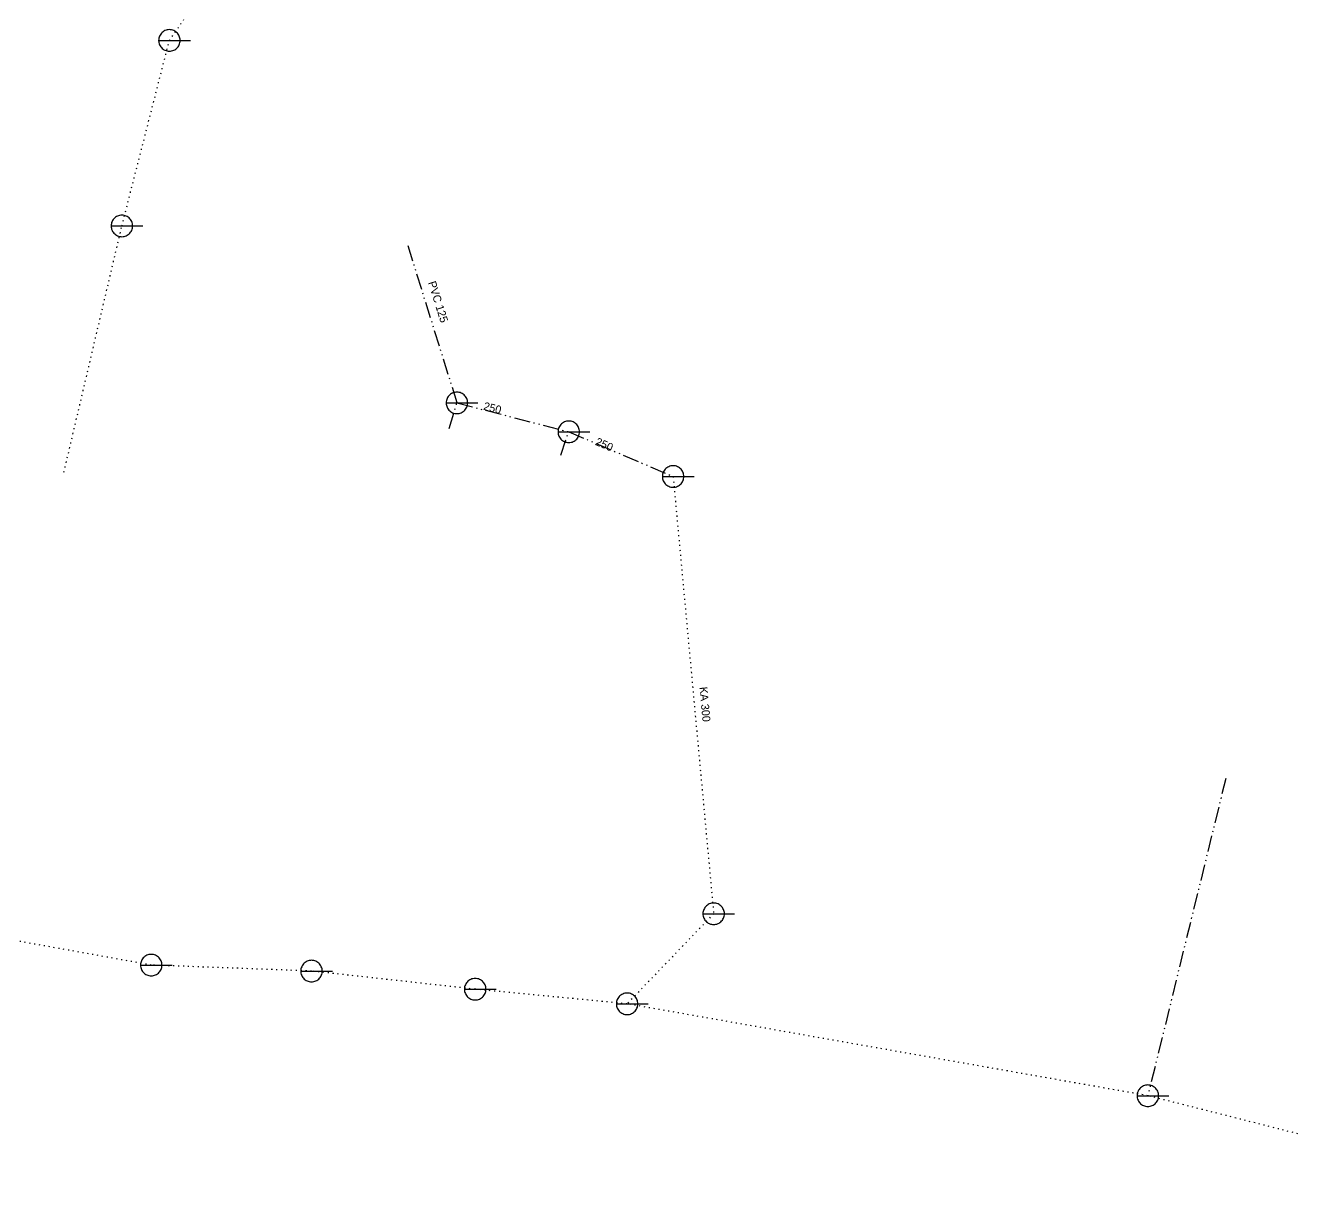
# Model space of a CAD drawing. Extents: x -688177 to -687620, y -1056713 to -1056287.
# Drawn here: x -688067.1 to -687948.5, y -1056712.1 to -1056603.9 of the extents above; entities that cross this region are included whole.
import ezdxf

# ---------------------------------------------------------------- set-up
doc = ezdxf.new("R2010")
doc.units = 0
doc.header["$LTSCALE"] = 0.3
doc.linetypes.add('DASH_DOUBLE_DOT', pattern=[9.2, 5, -1.2, 0.3, -1.2, 0.3, -1.2])
doc.linetypes.add('DOTTED', pattern=[1.5, 0.3, -1.2])
for name, color, linetype, lineweight in [('12', 7, 'Continuous', 13), ('31', 7, 'DOTTED', 13), ('41', 7, 'DOTTED', 13), ('45', 7, 'DASH_DOUBLE_DOT', 13), ('46', 7, 'DOTTED', 13), ('51', 7, 'DASH_DOUBLE_DOT', 13)]:
    doc.layers.add(name, color=color, linetype=linetype, lineweight=lineweight)
doc.layers.add('18', color=7, linetype='Continuous')
doc.layers.add('19', color=7, linetype='Continuous')

msp = doc.modelspace()

# ---------------------------------------------------------------- linework, layer by layer
at = {"layer": '12'}
for p, q in [((-688054.638, -1056605.28), (-688051.662, -1056605.28)), ((-688059.088, -1056622.67), (-688056.112, -1056622.67)), ((-688027.688, -1056639.25), (-688024.712, -1056639.25)), ((-688017.208, -1056641.96), (-688014.232, -1056641.96)), ((-688007.428, -1056646.15), (-688004.452, -1056646.15)), ((-688003.628, -1056687.13), (-688000.652, -1056687.13)), ((-688056.338, -1056691.94), (-688053.362, -1056691.94)), ((-688041.318, -1056692.5), (-688038.342, -1056692.5)), ((-688025.978, -1056694.2), (-688023.002, -1056694.2)), ((-688011.738, -1056695.57), (-688008.762, -1056695.57)), ((-687962.938, -1056704.18), (-687959.962, -1056704.18))]:
    msp.add_line(p, q, dxfattribs=at)
for points in [[(-688053.63, -1056604.272), (-688053.735, -1056604.278), (-688053.839, -1056604.294), (-688053.941, -1056604.322), (-688054.04, -1056604.36), (-688054.134, -1056604.407), (-688054.222, -1056604.465), (-688054.304, -1056604.531), (-688054.379, -1056604.606), (-688054.445, -1056604.688), (-688054.503, -1056604.776), (-688054.55, -1056604.87), (-688054.588, -1056604.969), (-688054.616, -1056605.071), (-688054.632, -1056605.175), (-688054.638, -1056605.28), (-688054.632, -1056605.385), (-688054.616, -1056605.49), (-688054.588, -1056605.592), (-688054.55, -1056605.69), (-688054.503, -1056605.784), (-688054.445, -1056605.873), (-688054.379, -1056605.955), (-688054.304, -1056606.029), (-688054.222, -1056606.095), (-688054.134, -1056606.153), (-688054.04, -1056606.201), (-688053.941, -1056606.239), (-688053.839, -1056606.266), (-688053.735, -1056606.282), (-688053.63, -1056606.288), (-688053.525, -1056606.282), (-688053.42, -1056606.266), (-688053.318, -1056606.239), (-688053.22, -1056606.201), (-688053.126, -1056606.153), (-688053.037, -1056606.095), (-688052.955, -1056606.029), (-688052.881, -1056605.955), (-688052.815, -1056605.873), (-688052.757, -1056605.784), (-688052.709, -1056605.69), (-688052.671, -1056605.592), (-688052.644, -1056605.49), (-688052.628, -1056605.385), (-688052.622, -1056605.28), (-688052.628, -1056605.175), (-688052.644, -1056605.071), (-688052.671, -1056604.969), (-688052.709, -1056604.87), (-688052.757, -1056604.776), (-688052.815, -1056604.688), (-688052.881, -1056604.606), (-688052.955, -1056604.531), (-688053.037, -1056604.465), (-688053.126, -1056604.407), (-688053.22, -1056604.36), (-688053.318, -1056604.322), (-688053.42, -1056604.294), (-688053.525, -1056604.278)], [(-688058.08, -1056621.662), (-688058.185, -1056621.668), (-688058.289, -1056621.684), (-688058.391, -1056621.712), (-688058.49, -1056621.75), (-688058.584, -1056621.797), (-688058.672, -1056621.855), (-688058.754, -1056621.921), (-688058.829, -1056621.996), (-688058.895, -1056622.078), (-688058.953, -1056622.166), (-688059, -1056622.26), (-688059.038, -1056622.359), (-688059.066, -1056622.461), (-688059.082, -1056622.565), (-688059.088, -1056622.67), (-688059.082, -1056622.775), (-688059.066, -1056622.88), (-688059.038, -1056622.982), (-688059, -1056623.08), (-688058.953, -1056623.174), (-688058.895, -1056623.263), (-688058.829, -1056623.345), (-688058.754, -1056623.419), (-688058.672, -1056623.485), (-688058.584, -1056623.543), (-688058.49, -1056623.591), (-688058.391, -1056623.629), (-688058.289, -1056623.656), (-688058.185, -1056623.672), (-688058.08, -1056623.678), (-688057.975, -1056623.672), (-688057.87, -1056623.656), (-688057.768, -1056623.629), (-688057.67, -1056623.591), (-688057.576, -1056623.543), (-688057.487, -1056623.485), (-688057.405, -1056623.419), (-688057.331, -1056623.345), (-688057.265, -1056623.263), (-688057.207, -1056623.174), (-688057.159, -1056623.08), (-688057.121, -1056622.982), (-688057.094, -1056622.88), (-688057.078, -1056622.775), (-688057.072, -1056622.67), (-688057.078, -1056622.565), (-688057.094, -1056622.461), (-688057.121, -1056622.359), (-688057.159, -1056622.26), (-688057.207, -1056622.166), (-688057.265, -1056622.078), (-688057.331, -1056621.996), (-688057.405, -1056621.921), (-688057.487, -1056621.855), (-688057.576, -1056621.797), (-688057.67, -1056621.75), (-688057.768, -1056621.712), (-688057.87, -1056621.684), (-688057.975, -1056621.668)], [(-688026.68, -1056638.242), (-688026.785, -1056638.248), (-688026.889, -1056638.264), (-688026.991, -1056638.292), (-688027.09, -1056638.33), (-688027.184, -1056638.377), (-688027.272, -1056638.435), (-688027.354, -1056638.501), (-688027.429, -1056638.576), (-688027.495, -1056638.658), (-688027.553, -1056638.746), (-688027.6, -1056638.84), (-688027.638, -1056638.939), (-688027.666, -1056639.041), (-688027.682, -1056639.145), (-688027.688, -1056639.25), (-688027.682, -1056639.355), (-688027.666, -1056639.46), (-688027.638, -1056639.562), (-688027.6, -1056639.66), (-688027.553, -1056639.754), (-688027.495, -1056639.843), (-688027.429, -1056639.925), (-688027.354, -1056639.999), (-688027.272, -1056640.065), (-688027.184, -1056640.123), (-688027.09, -1056640.171), (-688026.991, -1056640.209), (-688026.889, -1056640.236), (-688026.785, -1056640.252), (-688026.68, -1056640.258), (-688026.575, -1056640.252), (-688026.47, -1056640.236), (-688026.368, -1056640.209), (-688026.27, -1056640.171), (-688026.176, -1056640.123), (-688026.087, -1056640.065), (-688026.005, -1056639.999), (-688025.931, -1056639.925), (-688025.865, -1056639.843), (-688025.807, -1056639.754), (-688025.759, -1056639.66), (-688025.721, -1056639.562), (-688025.694, -1056639.46), (-688025.678, -1056639.355), (-688025.672, -1056639.25), (-688025.678, -1056639.145), (-688025.694, -1056639.041), (-688025.721, -1056638.939), (-688025.759, -1056638.84), (-688025.807, -1056638.746), (-688025.865, -1056638.658), (-688025.931, -1056638.576), (-688026.005, -1056638.501), (-688026.087, -1056638.435), (-688026.176, -1056638.377), (-688026.27, -1056638.33), (-688026.368, -1056638.292), (-688026.47, -1056638.264), (-688026.575, -1056638.248)], [(-688016.2, -1056640.952), (-688016.305, -1056640.958), (-688016.409, -1056640.974), (-688016.511, -1056641.002), (-688016.61, -1056641.04), (-688016.704, -1056641.087), (-688016.792, -1056641.145), (-688016.874, -1056641.211), (-688016.949, -1056641.286), (-688017.015, -1056641.368), (-688017.073, -1056641.456), (-688017.12, -1056641.55), (-688017.158, -1056641.649), (-688017.186, -1056641.751), (-688017.202, -1056641.855), (-688017.208, -1056641.96), (-688017.202, -1056642.065), (-688017.186, -1056642.17), (-688017.158, -1056642.272), (-688017.12, -1056642.37), (-688017.073, -1056642.464), (-688017.015, -1056642.553), (-688016.949, -1056642.635), (-688016.874, -1056642.709), (-688016.792, -1056642.775), (-688016.704, -1056642.833), (-688016.61, -1056642.881), (-688016.511, -1056642.919), (-688016.409, -1056642.946), (-688016.305, -1056642.962), (-688016.2, -1056642.968), (-688016.095, -1056642.962), (-688015.99, -1056642.946), (-688015.888, -1056642.919), (-688015.79, -1056642.881), (-688015.696, -1056642.833), (-688015.607, -1056642.775), (-688015.525, -1056642.709), (-688015.451, -1056642.635), (-688015.385, -1056642.553), (-688015.327, -1056642.464), (-688015.279, -1056642.37), (-688015.241, -1056642.272), (-688015.214, -1056642.17), (-688015.198, -1056642.065), (-688015.192, -1056641.96), (-688015.198, -1056641.855), (-688015.214, -1056641.751), (-688015.241, -1056641.649), (-688015.279, -1056641.55), (-688015.327, -1056641.456), (-688015.385, -1056641.368), (-688015.451, -1056641.286), (-688015.525, -1056641.211), (-688015.607, -1056641.145), (-688015.696, -1056641.087), (-688015.79, -1056641.04), (-688015.888, -1056641.002), (-688015.99, -1056640.974), (-688016.095, -1056640.958)], [(-688006.42, -1056645.142), (-688006.525, -1056645.148), (-688006.629, -1056645.164), (-688006.731, -1056645.192), (-688006.83, -1056645.23), (-688006.924, -1056645.277), (-688007.012, -1056645.335), (-688007.094, -1056645.401), (-688007.169, -1056645.476), (-688007.235, -1056645.558), (-688007.293, -1056645.646), (-688007.34, -1056645.74), (-688007.378, -1056645.839), (-688007.406, -1056645.941), (-688007.422, -1056646.045), (-688007.428, -1056646.15), (-688007.422, -1056646.255), (-688007.406, -1056646.36), (-688007.378, -1056646.462), (-688007.34, -1056646.56), (-688007.293, -1056646.654), (-688007.235, -1056646.743), (-688007.169, -1056646.825), (-688007.094, -1056646.899), (-688007.012, -1056646.965), (-688006.924, -1056647.023), (-688006.83, -1056647.071), (-688006.731, -1056647.109), (-688006.629, -1056647.136), (-688006.525, -1056647.152), (-688006.42, -1056647.158), (-688006.315, -1056647.152), (-688006.21, -1056647.136), (-688006.108, -1056647.109), (-688006.01, -1056647.071), (-688005.916, -1056647.023), (-688005.827, -1056646.965), (-688005.745, -1056646.899), (-688005.671, -1056646.825), (-688005.605, -1056646.743), (-688005.547, -1056646.654), (-688005.499, -1056646.56), (-688005.461, -1056646.462), (-688005.434, -1056646.36), (-688005.418, -1056646.255), (-688005.412, -1056646.15), (-688005.418, -1056646.045), (-688005.434, -1056645.941), (-688005.461, -1056645.839), (-688005.499, -1056645.74), (-688005.547, -1056645.646), (-688005.605, -1056645.558), (-688005.671, -1056645.476), (-688005.745, -1056645.401), (-688005.827, -1056645.335), (-688005.916, -1056645.277), (-688006.01, -1056645.23), (-688006.108, -1056645.192), (-688006.21, -1056645.164), (-688006.315, -1056645.148)], [(-688002.62, -1056686.122), (-688002.725, -1056686.128), (-688002.829, -1056686.144), (-688002.931, -1056686.172), (-688003.03, -1056686.21), (-688003.124, -1056686.257), (-688003.212, -1056686.315), (-688003.294, -1056686.381), (-688003.369, -1056686.456), (-688003.435, -1056686.538), (-688003.493, -1056686.626), (-688003.54, -1056686.72), (-688003.578, -1056686.819), (-688003.606, -1056686.921), (-688003.622, -1056687.025), (-688003.628, -1056687.13), (-688003.622, -1056687.235), (-688003.606, -1056687.34), (-688003.578, -1056687.442), (-688003.54, -1056687.54), (-688003.493, -1056687.634), (-688003.435, -1056687.723), (-688003.369, -1056687.805), (-688003.294, -1056687.879), (-688003.212, -1056687.945), (-688003.124, -1056688.003), (-688003.03, -1056688.051), (-688002.931, -1056688.089), (-688002.829, -1056688.116), (-688002.725, -1056688.132), (-688002.62, -1056688.138), (-688002.515, -1056688.132), (-688002.41, -1056688.116), (-688002.308, -1056688.089), (-688002.21, -1056688.051), (-688002.116, -1056688.003), (-688002.027, -1056687.945), (-688001.945, -1056687.879), (-688001.871, -1056687.805), (-688001.805, -1056687.723), (-688001.747, -1056687.634), (-688001.699, -1056687.54), (-688001.661, -1056687.442), (-688001.634, -1056687.34), (-688001.618, -1056687.235), (-688001.612, -1056687.13), (-688001.618, -1056687.025), (-688001.634, -1056686.921), (-688001.661, -1056686.819), (-688001.699, -1056686.72), (-688001.747, -1056686.626), (-688001.805, -1056686.538), (-688001.871, -1056686.456), (-688001.945, -1056686.381), (-688002.027, -1056686.315), (-688002.116, -1056686.257), (-688002.21, -1056686.21), (-688002.308, -1056686.172), (-688002.41, -1056686.144), (-688002.515, -1056686.128)], [(-688055.33, -1056690.932), (-688055.435, -1056690.938), (-688055.539, -1056690.954), (-688055.641, -1056690.982), (-688055.74, -1056691.02), (-688055.834, -1056691.067), (-688055.922, -1056691.125), (-688056.004, -1056691.191), (-688056.079, -1056691.266), (-688056.145, -1056691.348), (-688056.203, -1056691.436), (-688056.25, -1056691.53), (-688056.288, -1056691.629), (-688056.316, -1056691.731), (-688056.332, -1056691.835), (-688056.338, -1056691.94), (-688056.332, -1056692.045), (-688056.316, -1056692.15), (-688056.288, -1056692.252), (-688056.25, -1056692.35), (-688056.203, -1056692.444), (-688056.145, -1056692.533), (-688056.079, -1056692.615), (-688056.004, -1056692.689), (-688055.922, -1056692.755), (-688055.834, -1056692.813), (-688055.74, -1056692.861), (-688055.641, -1056692.899), (-688055.539, -1056692.926), (-688055.435, -1056692.942), (-688055.33, -1056692.948), (-688055.225, -1056692.942), (-688055.12, -1056692.926), (-688055.018, -1056692.899), (-688054.92, -1056692.861), (-688054.826, -1056692.813), (-688054.737, -1056692.755), (-688054.655, -1056692.689), (-688054.581, -1056692.615), (-688054.515, -1056692.533), (-688054.457, -1056692.444), (-688054.409, -1056692.35), (-688054.371, -1056692.252), (-688054.344, -1056692.15), (-688054.328, -1056692.045), (-688054.322, -1056691.94), (-688054.328, -1056691.835), (-688054.344, -1056691.731), (-688054.371, -1056691.629), (-688054.409, -1056691.53), (-688054.457, -1056691.436), (-688054.515, -1056691.348), (-688054.581, -1056691.266), (-688054.655, -1056691.191), (-688054.737, -1056691.125), (-688054.826, -1056691.067), (-688054.92, -1056691.02), (-688055.018, -1056690.982), (-688055.12, -1056690.954), (-688055.225, -1056690.938)], [(-688040.31, -1056691.492), (-688040.415, -1056691.498), (-688040.519, -1056691.514), (-688040.621, -1056691.542), (-688040.72, -1056691.58), (-688040.814, -1056691.627), (-688040.902, -1056691.685), (-688040.984, -1056691.751), (-688041.059, -1056691.826), (-688041.125, -1056691.908), (-688041.183, -1056691.996), (-688041.23, -1056692.09), (-688041.268, -1056692.189), (-688041.296, -1056692.291), (-688041.312, -1056692.395), (-688041.318, -1056692.5), (-688041.312, -1056692.605), (-688041.296, -1056692.71), (-688041.268, -1056692.812), (-688041.23, -1056692.91), (-688041.183, -1056693.004), (-688041.125, -1056693.093), (-688041.059, -1056693.175), (-688040.984, -1056693.249), (-688040.902, -1056693.315), (-688040.814, -1056693.373), (-688040.72, -1056693.421), (-688040.621, -1056693.459), (-688040.519, -1056693.486), (-688040.415, -1056693.502), (-688040.31, -1056693.508), (-688040.205, -1056693.502), (-688040.1, -1056693.486), (-688039.998, -1056693.459), (-688039.9, -1056693.421), (-688039.806, -1056693.373), (-688039.717, -1056693.315), (-688039.635, -1056693.249), (-688039.561, -1056693.175), (-688039.495, -1056693.093), (-688039.437, -1056693.004), (-688039.389, -1056692.91), (-688039.351, -1056692.812), (-688039.324, -1056692.71), (-688039.308, -1056692.605), (-688039.302, -1056692.5), (-688039.308, -1056692.395), (-688039.324, -1056692.291), (-688039.351, -1056692.189), (-688039.389, -1056692.09), (-688039.437, -1056691.996), (-688039.495, -1056691.908), (-688039.561, -1056691.826), (-688039.635, -1056691.751), (-688039.717, -1056691.685), (-688039.806, -1056691.627), (-688039.9, -1056691.58), (-688039.998, -1056691.542), (-688040.1, -1056691.514), (-688040.205, -1056691.498)], [(-688024.97, -1056693.192), (-688025.075, -1056693.198), (-688025.179, -1056693.214), (-688025.281, -1056693.242), (-688025.38, -1056693.28), (-688025.474, -1056693.327), (-688025.562, -1056693.385), (-688025.644, -1056693.451), (-688025.719, -1056693.526), (-688025.785, -1056693.608), (-688025.843, -1056693.696), (-688025.89, -1056693.79), (-688025.928, -1056693.889), (-688025.956, -1056693.991), (-688025.972, -1056694.095), (-688025.978, -1056694.2), (-688025.972, -1056694.305), (-688025.956, -1056694.41), (-688025.928, -1056694.512), (-688025.89, -1056694.61), (-688025.843, -1056694.704), (-688025.785, -1056694.793), (-688025.719, -1056694.875), (-688025.644, -1056694.949), (-688025.562, -1056695.015), (-688025.474, -1056695.073), (-688025.38, -1056695.121), (-688025.281, -1056695.159), (-688025.179, -1056695.186), (-688025.075, -1056695.202), (-688024.97, -1056695.208), (-688024.865, -1056695.202), (-688024.76, -1056695.186), (-688024.658, -1056695.159), (-688024.56, -1056695.121), (-688024.466, -1056695.073), (-688024.377, -1056695.015), (-688024.295, -1056694.949), (-688024.221, -1056694.875), (-688024.155, -1056694.793), (-688024.097, -1056694.704), (-688024.049, -1056694.61), (-688024.011, -1056694.512), (-688023.984, -1056694.41), (-688023.968, -1056694.305), (-688023.962, -1056694.2), (-688023.968, -1056694.095), (-688023.984, -1056693.991), (-688024.011, -1056693.889), (-688024.049, -1056693.79), (-688024.097, -1056693.696), (-688024.155, -1056693.608), (-688024.221, -1056693.526), (-688024.295, -1056693.451), (-688024.377, -1056693.385), (-688024.466, -1056693.327), (-688024.56, -1056693.28), (-688024.658, -1056693.242), (-688024.76, -1056693.214), (-688024.865, -1056693.198)], [(-688010.73, -1056694.562), (-688010.835, -1056694.568), (-688010.939, -1056694.584), (-688011.041, -1056694.612), (-688011.14, -1056694.65), (-688011.234, -1056694.697), (-688011.322, -1056694.755), (-688011.404, -1056694.821), (-688011.479, -1056694.896), (-688011.545, -1056694.978), (-688011.603, -1056695.066), (-688011.65, -1056695.16), (-688011.688, -1056695.259), (-688011.716, -1056695.361), (-688011.732, -1056695.465), (-688011.738, -1056695.57), (-688011.732, -1056695.675), (-688011.716, -1056695.78), (-688011.688, -1056695.882), (-688011.65, -1056695.98), (-688011.603, -1056696.074), (-688011.545, -1056696.163), (-688011.479, -1056696.245), (-688011.404, -1056696.319), (-688011.322, -1056696.385), (-688011.234, -1056696.443), (-688011.14, -1056696.491), (-688011.041, -1056696.529), (-688010.939, -1056696.556), (-688010.835, -1056696.572), (-688010.73, -1056696.578), (-688010.625, -1056696.572), (-688010.52, -1056696.556), (-688010.418, -1056696.529), (-688010.32, -1056696.491), (-688010.226, -1056696.443), (-688010.137, -1056696.385), (-688010.055, -1056696.319), (-688009.981, -1056696.245), (-688009.915, -1056696.163), (-688009.857, -1056696.074), (-688009.809, -1056695.98), (-688009.771, -1056695.882), (-688009.744, -1056695.78), (-688009.728, -1056695.675), (-688009.722, -1056695.57), (-688009.728, -1056695.465), (-688009.744, -1056695.361), (-688009.771, -1056695.259), (-688009.809, -1056695.16), (-688009.857, -1056695.066), (-688009.915, -1056694.978), (-688009.981, -1056694.896), (-688010.055, -1056694.821), (-688010.137, -1056694.755), (-688010.226, -1056694.697), (-688010.32, -1056694.65), (-688010.418, -1056694.612), (-688010.52, -1056694.584), (-688010.625, -1056694.568)], [(-687961.93, -1056703.172), (-687962.035, -1056703.178), (-687962.139, -1056703.194), (-687962.241, -1056703.222), (-687962.34, -1056703.26), (-687962.434, -1056703.307), (-687962.522, -1056703.365), (-687962.604, -1056703.431), (-687962.679, -1056703.506), (-687962.745, -1056703.588), (-687962.803, -1056703.676), (-687962.85, -1056703.77), (-687962.888, -1056703.869), (-687962.916, -1056703.971), (-687962.932, -1056704.075), (-687962.938, -1056704.18), (-687962.932, -1056704.285), (-687962.916, -1056704.39), (-687962.888, -1056704.492), (-687962.85, -1056704.59), (-687962.803, -1056704.684), (-687962.745, -1056704.773), (-687962.679, -1056704.855), (-687962.604, -1056704.929), (-687962.522, -1056704.995), (-687962.434, -1056705.053), (-687962.34, -1056705.101), (-687962.241, -1056705.139), (-687962.139, -1056705.166), (-687962.035, -1056705.182), (-687961.93, -1056705.188), (-687961.825, -1056705.182), (-687961.72, -1056705.166), (-687961.618, -1056705.139), (-687961.52, -1056705.101), (-687961.426, -1056705.053), (-687961.337, -1056704.995), (-687961.255, -1056704.929), (-687961.181, -1056704.855), (-687961.115, -1056704.773), (-687961.057, -1056704.684), (-687961.009, -1056704.59), (-687960.971, -1056704.492), (-687960.944, -1056704.39), (-687960.928, -1056704.285), (-687960.922, -1056704.18), (-687960.928, -1056704.075), (-687960.944, -1056703.971), (-687960.971, -1056703.869), (-687961.009, -1056703.77), (-687961.057, -1056703.676), (-687961.115, -1056703.588), (-687961.181, -1056703.506), (-687961.255, -1056703.431), (-687961.337, -1056703.365), (-687961.426, -1056703.307), (-687961.52, -1056703.26), (-687961.618, -1056703.222), (-687961.72, -1056703.194), (-687961.825, -1056703.178)]]:
    msp.add_lwpolyline(points, close=True, dxfattribs=at)
at = {"layer": '31'}
msp.add_line((-688063.51, -1056645.75), (-688058.08, -1056622.67), dxfattribs=at)
at = {"layer": '41'}
for p, q in [((-687961.93, -1056704.18), (-688010.73, -1056695.57)), ((-687930.93, -1056712.05), (-687961.93, -1056704.18))]:
    msp.add_line(p, q, dxfattribs=at)
for points in [[(-688058.08, -1056622.67), (-688053.63, -1056605.28), (-688027.55, -1056567.82)], [(-688040.3, -1056692.5), (-688055.33, -1056691.94), (-688071.98, -1056688.94)], [(-688010.73, -1056695.57), (-688024.97, -1056694.2), (-688040.31, -1056692.5)]]:
    msp.add_lwpolyline(points, dxfattribs=at)
at = {"layer": '45'}
msp.add_lwpolyline([(-688026.68, -1056639.25), (-688016.2, -1056641.96), (-688006.42, -1056646.15)], dxfattribs=at)
at = {"layer": '46', "linetype": 'DASH_DOUBLE_DOT'}
msp.add_line((-687954.63, -1056674.44), (-687961.93, -1056704.18), dxfattribs=at)
at = {"layer": '46'}
msp.add_lwpolyline([(-688006.42, -1056646.15), (-688002.62, -1056687.13), (-688010.73, -1056695.57)], dxfattribs=at)
at = {"layer": '51'}
for p, q in [((-688031.29, -1056624.51), (-688026.68, -1056639.25)), ((-688027.41, -1056641.65), (-688026.68, -1056639.25)), ((-688016.93, -1056644.15), (-688016.23, -1056641.96))]:
    msp.add_line(p, q, dxfattribs=at)

# ---------------------------------------------------------------- texts
at = {"layer": '18'}
for s, rotation, p in [('250', 345.502, (-688024.251, -1056639.882)), ('250', 336.808, (-688013.783, -1056643.162)), ('KA 300', 275.298, (-688003.959, -1056665.894))]:
    msp.add_text(s, height=0.75, rotation=rotation, dxfattribs=at).set_placement(p)
at = {"layer": '19'}
msp.add_text('PVC 125', height=0.75, rotation=287.367, dxfattribs=at).set_placement((-688029.396, -1056627.973))

doc.saveas('drawing.dxf')
